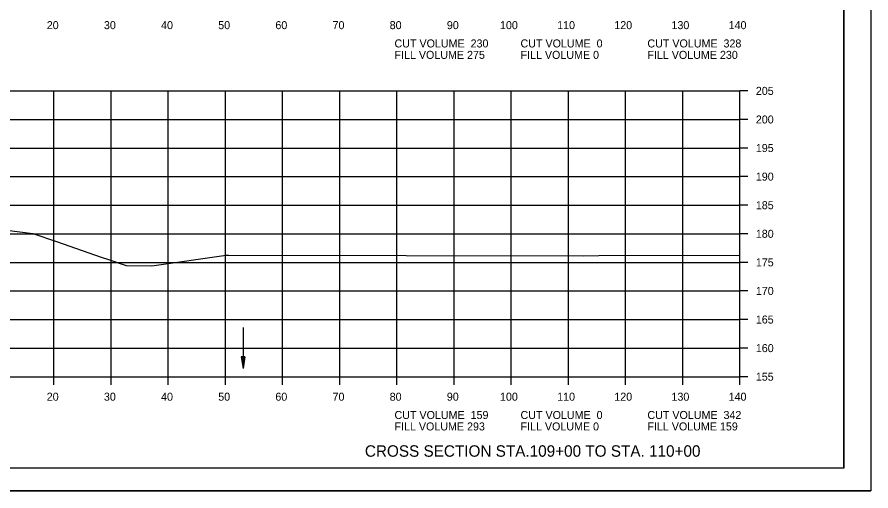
# Model space of a CAD drawing. Extents: x 1372132 to 1372465, y 380083 to 381790.
# Drawn here: x 1372315.6 to 1372464.9, y 381363.5 to 381446.4 of the extents above; entities that cross this region are included whole.
import ezdxf

# ---------------------------------------------------------------- set-up
doc = ezdxf.new("R2010")
doc.units = 0
for name, color, linetype in [('R_Axis', 7, 'Continuous'), ('R_Axis Annot', 7, 'Continuous'), ('R_Border', 7, 'Continuous'), ('R_Dimension', 7, 'Continuous'), ('R_Draft', 7, 'Continuous'), ('R_Exist Surface', 7, 'Continuous'), ('R_Grid', 7, 'Continuous'), ('R_No Plot', 7, 'Continuous')]:
    doc.layers.add(name, color=color, linetype=linetype)

msp = doc.modelspace()

# ---------------------------------------------------------------- linework, layer by layer
at = {"layer": 'R_Axis'}
for p, q in [((1372442.01, 381383.5), (1372442.01, 381433.5)), ((1372443.41, 381433.5), (1372442.01, 381433.5)), ((1372443.41, 381428.5), (1372442.01, 381428.5)), ((1372443.41, 381423.5), (1372442.01, 381423.5)), ((1372443.41, 381418.5), (1372442.01, 381418.5)), ((1372443.41, 381413.5), (1372442.01, 381413.5)), ((1372443.41, 381408.5), (1372442.01, 381408.5)), ((1372443.41, 381403.5), (1372442.01, 381403.5)), ((1372443.41, 381398.5), (1372442.01, 381398.5)), ((1372443.41, 381393.5), (1372442.01, 381393.5)), ((1372443.41, 381388.5), (1372442.01, 381388.5)), ((1372162.01, 381383.5), (1372442.01, 381383.5)), ((1372322.01, 381382.1), (1372322.01, 381383.5)), ((1372332.01, 381382.1), (1372332.01, 381383.5)), ((1372342.01, 381382.1), (1372342.01, 381383.5)), ((1372352.01, 381382.1), (1372352.01, 381383.5)), ((1372362.01, 381382.1), (1372362.01, 381383.5)), ((1372372.01, 381382.1), (1372372.01, 381383.5)), ((1372382.01, 381382.1), (1372382.01, 381383.5)), ((1372392.01, 381382.1), (1372392.01, 381383.5)), ((1372402.01, 381382.1), (1372402.01, 381383.5)), ((1372412.01, 381382.1), (1372412.01, 381383.5)), ((1372422.01, 381382.1), (1372422.01, 381383.5)), ((1372432.01, 381382.1), (1372432.01, 381383.5)), ((1372442.01, 381382.1), (1372442.01, 381383.5)), ((1372443.41, 381383.5), (1372442.01, 381383.5))]:
    msp.add_line(p, q, dxfattribs=at)
at = {"layer": 'R_Border'}
for q in [(1372460.19, 381572.96), (1372144.01, 381367.5)]:
    msp.add_line((1372460.19, 381367.5), q, dxfattribs=at)
at = {"layer": 'R_Dimension'}
for p, q in [((1372354.79, 381386.96), (1372355.09, 381384.96)), ((1372355.39, 381386.96), (1372354.79, 381386.96)), ((1372354.79, 381386.96), (1372355.09, 381384.96)), ((1372355.39, 381386.96), (1372354.79, 381386.96)), ((1372354.84, 381386.96), (1372355.09, 381385.3)), ((1372354.84, 381386.96), (1372355.09, 381385.3)), ((1372354.89, 381386.96), (1372355.09, 381385.64)), ((1372354.89, 381386.96), (1372355.09, 381385.64)), ((1372354.94, 381386.96), (1372355.09, 381385.97)), ((1372354.94, 381386.96), (1372355.09, 381385.97)), ((1372355, 381386.96), (1372355.09, 381386.31)), ((1372355, 381386.96), (1372355.09, 381386.31)), ((1372355.05, 381386.96), (1372355.09, 381386.65)), ((1372355.05, 381386.96), (1372355.09, 381386.65)), ((1372355.39, 381386.96), (1372355.09, 381384.96)), ((1372355.19, 381386.96), (1372355.09, 381386.31)), ((1372355.29, 381386.96), (1372355.09, 381385.64)), ((1372355.34, 381386.96), (1372355.09, 381385.3)), ((1372355.24, 381386.96), (1372355.09, 381385.97)), ((1372355.14, 381386.96), (1372355.09, 381386.65)), ((1372355.39, 381386.96), (1372355.09, 381384.96)), ((1372355.19, 381386.96), (1372355.09, 381386.31)), ((1372355.29, 381386.96), (1372355.09, 381385.64)), ((1372355.34, 381386.96), (1372355.09, 381385.3)), ((1372355.24, 381386.96), (1372355.09, 381385.97)), ((1372355.14, 381386.96), (1372355.09, 381386.65))]:
    msp.add_line(p, q, dxfattribs=at)
at = {"layer": 'R_Draft'}
msp.add_line((1372355.09, 381392.1), (1372355.09, 381384.96), dxfattribs=at)
at = {"layer": 'R_Exist Surface'}
msp.add_lwpolyline([(1372312.25, 381409.29), (1372316.5, 381408.8), (1372318.34, 381408.56), (1372322.44, 381407.15), (1372330.25, 381404.39), (1372331.55, 381403.98), (1372334.62, 381402.94), (1372339.12, 381402.92), (1372352.13, 381404.74), (1372352.14, 381404.74), (1372352.17, 381404.74), (1372352.54, 381404.74), (1372414.73, 381404.67), (1372417.35, 381404.68), (1372442.01, 381404.77)], dxfattribs=at)
at = {"layer": 'R_Grid'}
for p, q in [((1372162.01, 381433.5), (1372442.01, 381433.5)), ((1372322.01, 381383.5), (1372322.01, 381433.5)), ((1372332.01, 381383.5), (1372332.01, 381433.5)), ((1372342.01, 381383.5), (1372342.01, 381433.5)), ((1372352.01, 381383.5), (1372352.01, 381433.5)), ((1372362.01, 381383.5), (1372362.01, 381433.5)), ((1372372.01, 381383.5), (1372372.01, 381433.5)), ((1372382.01, 381383.5), (1372382.01, 381433.5)), ((1372392.01, 381383.5), (1372392.01, 381433.5)), ((1372402.01, 381383.5), (1372402.01, 381433.5)), ((1372412.01, 381383.5), (1372412.01, 381433.5)), ((1372422.01, 381383.5), (1372422.01, 381433.5)), ((1372432.01, 381383.5), (1372432.01, 381433.5)), ((1372442.01, 381383.5), (1372442.01, 381433.5)), ((1372162.01, 381428.5), (1372442.01, 381428.5)), ((1372162.01, 381423.5), (1372442.01, 381423.5)), ((1372162.01, 381418.5), (1372442.01, 381418.5)), ((1372162.01, 381413.5), (1372442.01, 381413.5)), ((1372162.01, 381408.5), (1372442.01, 381408.5)), ((1372162.01, 381403.5), (1372442.01, 381403.5)), ((1372162.01, 381398.5), (1372442.01, 381398.5)), ((1372162.01, 381393.5), (1372442.01, 381393.5)), ((1372162.01, 381388.5), (1372442.01, 381388.5)), ((1372162.01, 381383.5), (1372442.01, 381383.5))]:
    msp.add_line(p, q, dxfattribs=at)
at = {"layer": 'R_No Plot'}
msp.add_line((1372131.61, 381363.52), (1372464.95, 381363.52), dxfattribs=at)
for points in [[(1372131.61, 381576.86), (1372464.95, 381576.86), (1372464.95, 381363.52), (1372131.61, 381363.52)], [(1372377.93, 381572.96), (1372377.93, 381563.08), (1372413.67, 381563.08), (1372413.67, 381560.16), (1372436.87, 381560.16), (1372436.87, 381535.83), (1372460.19, 381535.83), (1372460.19, 381367.5), (1372144.01, 381367.5), (1372144.01, 381572.96)]]:
    msp.add_lwpolyline(points, close=True, dxfattribs=at)

# ---------------------------------------------------------------- texts
at = {"layer": 'R_Axis Annot'}
for s, p in [('20', (1372320.75, 381444.3)), ('30', (1372330.75, 381444.3)), ('40', (1372340.75, 381444.3)), ('50', (1372350.75, 381444.3)), ('60', (1372360.75, 381444.3)), ('70', (1372370.75, 381444.3)), ('80', (1372380.75, 381444.3)), ('90', (1372390.75, 381444.3)), ('100', (1372400.05, 381444.3)), ('110', (1372410.05, 381444.3)), ('120', (1372420.05, 381444.3)), ('130', (1372430.05, 381444.3)), ('140', (1372440.05, 381444.3)), ('CUT VOLUME  230', (1372381.59, 381441.1)), ('CUT VOLUME  0', (1372403.64, 381441.1)), ('CUT VOLUME  328', (1372425.84, 381441.1)), ('FILL VOLUME 275', (1372381.59, 381439.1)), ('FILL VOLUME 0', (1372403.64, 381439.1)), ('FILL VOLUME 230', (1372425.84, 381439.1)), ('205', (1372444.81, 381432.8)), ('200', (1372444.81, 381427.8)), ('195', (1372444.81, 381422.8)), ('190', (1372444.81, 381417.8)), ('185', (1372444.81, 381412.8)), ('180', (1372444.81, 381407.8)), ('175', (1372444.81, 381402.8)), ('170', (1372444.81, 381397.8)), ('165', (1372444.81, 381392.8)), ('160', (1372444.81, 381387.8)), ('155', (1372444.81, 381382.8)), ('20', (1372320.75, 381379.3)), ('30', (1372330.75, 381379.3)), ('40', (1372340.75, 381379.3)), ('50', (1372350.75, 381379.3)), ('60', (1372360.75, 381379.3)), ('70', (1372370.75, 381379.3)), ('80', (1372380.75, 381379.3)), ('90', (1372390.75, 381379.3)), ('100', (1372400.05, 381379.3)), ('110', (1372410.05, 381379.3)), ('120', (1372420.05, 381379.3)), ('130', (1372430.05, 381379.3)), ('140', (1372440.05, 381379.3)), ('CUT VOLUME  159', (1372381.59, 381376.1)), ('CUT VOLUME  0', (1372403.64, 381376.1)), ('CUT VOLUME  342', (1372425.84, 381376.1)), ('FILL VOLUME 293', (1372381.59, 381374.1)), ('FILL VOLUME 0', (1372403.64, 381374.1)), ('FILL VOLUME 159', (1372425.84, 381374.1))]:
    msp.add_text(s, height=1.4, dxfattribs=at).set_placement(p)
at = {"layer": 'R_Draft'}
msp.add_text('CROSS SECTION STA.109+00 TO STA. 110+00', height=2, dxfattribs=at).set_placement((1372376.41, 381369.5))

doc.saveas('drawing.dxf')
